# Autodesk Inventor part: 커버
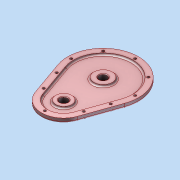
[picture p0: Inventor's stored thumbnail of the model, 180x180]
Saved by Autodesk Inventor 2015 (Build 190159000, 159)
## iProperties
Created: 2024-05
Part Number: 커버
Material: 일반
Document SubType Name: Modeling
Designer: Administrator
Density: 1 g/cm^3
Appearance: 기본값
Author: Administrator
Author: jhkim
Creation Date: 2024-05-07
Sending System: Autodesk Inventor 2025
Preprocessor: ST-DEVELOPER v20
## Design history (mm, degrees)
node "커버1"
node "솔리드1"
node "기준1"
